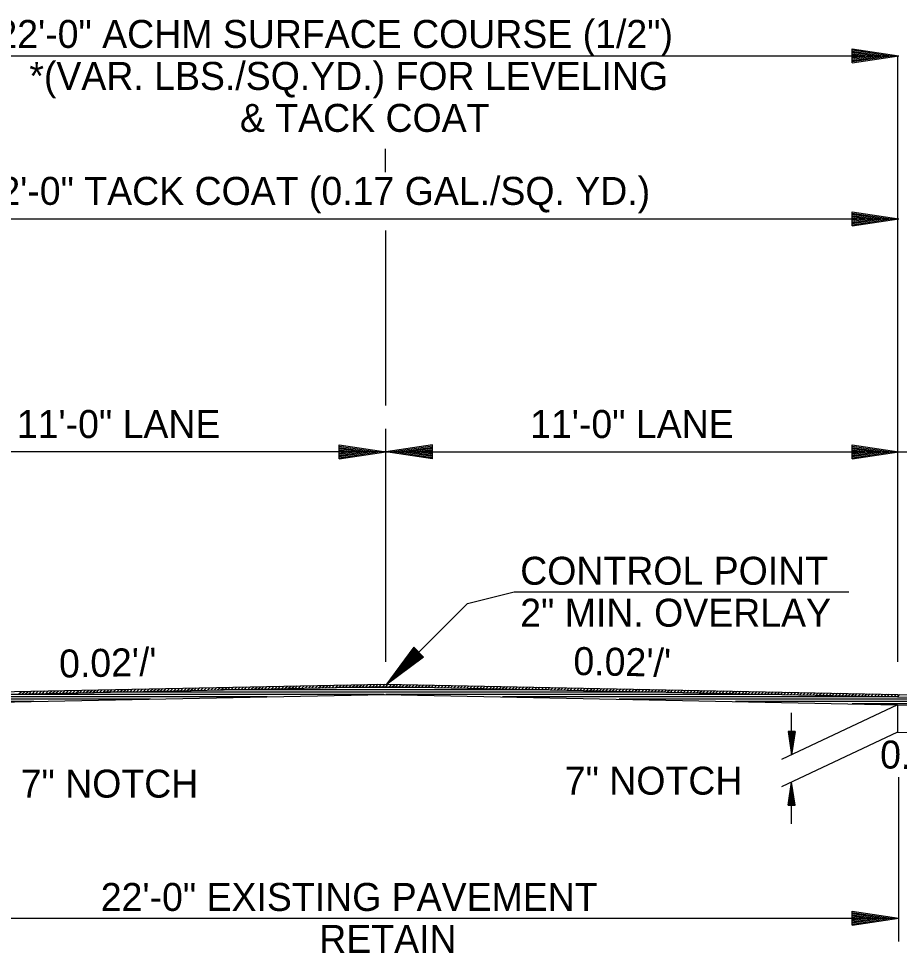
# Model space of a CAD drawing. Extents: x 2263886 to 2266026, y -3122850 to -3121850.
# Drawn here: x 2265472.89 to 2265491.77, y -3122426.95 to -3122407.14 of the extents above; entities that cross this region are included whole.
import ezdxf

# ---------------------------------------------------------------- set-up
doc = ezdxf.new("R2010")
doc.units = 0
doc.layers.add('R_Border Notes', color=7, linetype='Continuous')
doc.layers.add('R_Border Prem', color=7, linetype='Continuous')

msp = doc.modelspace()

# ---------------------------------------------------------------- linework, layer by layer
at = {"layer": 'R_Border Notes'}
for p, q in [((2265469.74, -3122421.686), (2265480.738, -3122421.466)), ((2265469.741, -3122421.634), (2265480.739, -3122421.414)), ((2265472.9, -3122421.622), (2265472.953, -3122421.569)), ((2265472.972, -3122421.621), (2265473.025, -3122421.568)), ((2265473.044, -3122421.62), (2265473.097, -3122421.567)), ((2265473.116, -3122421.618), (2265473.169, -3122421.565)), ((2265473.189, -3122421.617), (2265473.242, -3122421.564)), ((2265473.261, -3122421.615), (2265473.314, -3122421.562)), ((2265473.333, -3122421.614), (2265473.386, -3122421.561)), ((2265473.405, -3122421.612), (2265473.458, -3122421.559)), ((2265473.477, -3122421.611), (2265473.53, -3122421.558)), ((2265473.549, -3122421.609), (2265473.602, -3122421.556)), ((2265473.621, -3122421.608), (2265473.674, -3122421.555)), ((2265473.694, -3122421.607), (2265473.747, -3122421.554)), ((2265473.766, -3122421.605), (2265473.819, -3122421.552)), ((2265473.838, -3122421.604), (2265473.891, -3122421.551)), ((2265473.91, -3122421.602), (2265473.963, -3122421.549)), ((2265473.982, -3122421.601), (2265474.035, -3122421.548)), ((2265474.054, -3122421.599), (2265474.107, -3122421.546)), ((2265474.127, -3122421.598), (2265474.18, -3122421.545)), ((2265474.199, -3122421.596), (2265474.252, -3122421.543)), ((2265474.271, -3122421.595), (2265474.324, -3122421.542)), ((2265474.343, -3122421.594), (2265474.396, -3122421.541)), ((2265474.415, -3122421.592), (2265474.468, -3122421.539)), ((2265474.487, -3122421.591), (2265474.54, -3122421.538)), ((2265474.559, -3122421.589), (2265474.612, -3122421.536)), ((2265474.632, -3122421.588), (2265474.685, -3122421.535)), ((2265474.704, -3122421.586), (2265474.757, -3122421.533)), ((2265474.776, -3122421.585), (2265474.829, -3122421.532)), ((2265474.848, -3122421.583), (2265474.901, -3122421.53)), ((2265474.92, -3122421.582), (2265474.973, -3122421.529)), ((2265474.992, -3122421.581), (2265475.045, -3122421.528)), ((2265475.065, -3122421.579), (2265475.118, -3122421.526)), ((2265475.137, -3122421.578), (2265475.19, -3122421.525)), ((2265475.209, -3122421.576), (2265475.262, -3122421.523)), ((2265475.281, -3122421.575), (2265475.334, -3122421.522)), ((2265475.353, -3122421.573), (2265475.406, -3122421.52)), ((2265475.425, -3122421.572), (2265475.478, -3122421.519)), ((2265475.497, -3122421.57), (2265475.55, -3122421.517)), ((2265475.57, -3122421.569), (2265475.623, -3122421.516)), ((2265475.642, -3122421.568), (2265475.695, -3122421.515)), ((2265475.714, -3122421.566), (2265475.767, -3122421.513)), ((2265475.786, -3122421.565), (2265475.839, -3122421.512)), ((2265475.858, -3122421.563), (2265475.911, -3122421.51)), ((2265475.93, -3122421.562), (2265475.983, -3122421.509)), ((2265476.003, -3122421.56), (2265476.056, -3122421.507)), ((2265476.075, -3122421.559), (2265476.128, -3122421.506)), ((2265476.147, -3122421.557), (2265476.2, -3122421.504)), ((2265476.219, -3122421.556), (2265476.272, -3122421.503)), ((2265476.291, -3122421.555), (2265476.344, -3122421.502)), ((2265476.363, -3122421.553), (2265476.416, -3122421.5)), ((2265476.435, -3122421.552), (2265476.488, -3122421.499)), ((2265476.508, -3122421.55), (2265476.561, -3122421.497)), ((2265476.58, -3122421.549), (2265476.633, -3122421.496)), ((2265476.652, -3122421.547), (2265476.705, -3122421.494)), ((2265476.724, -3122421.546), (2265476.777, -3122421.493)), ((2265476.796, -3122421.545), (2265476.849, -3122421.491)), ((2265476.868, -3122421.543), (2265476.921, -3122421.49)), ((2265476.941, -3122421.542), (2265476.994, -3122421.489)), ((2265477.013, -3122421.54), (2265477.066, -3122421.487)), ((2265477.085, -3122421.539), (2265477.138, -3122421.486)), ((2265477.157, -3122421.537), (2265477.21, -3122421.484)), ((2265484.259, -3122421.536), (2265477.217, -3122421.536)), ((2265477.229, -3122421.536), (2265477.282, -3122421.483)), ((2265477.301, -3122421.534), (2265477.354, -3122421.481)), ((2265477.373, -3122421.533), (2265477.426, -3122421.48)), ((2265477.446, -3122421.532), (2265477.499, -3122421.478)), ((2265477.518, -3122421.53), (2265477.571, -3122421.477)), ((2265477.59, -3122421.529), (2265477.643, -3122421.476)), ((2265477.662, -3122421.527), (2265477.715, -3122421.474)), ((2265477.734, -3122421.526), (2265477.787, -3122421.473)), ((2265477.806, -3122421.524), (2265477.859, -3122421.471)), ((2265477.879, -3122421.523), (2265477.932, -3122421.47)), ((2265477.951, -3122421.521), (2265478.004, -3122421.468)), ((2265478.023, -3122421.52), (2265478.076, -3122421.467)), ((2265478.095, -3122421.519), (2265478.148, -3122421.465)), ((2265478.167, -3122421.517), (2265478.22, -3122421.464)), ((2265478.239, -3122421.516), (2265478.292, -3122421.463)), ((2265478.311, -3122421.514), (2265478.364, -3122421.461)), ((2265478.384, -3122421.513), (2265478.437, -3122421.46)), ((2265478.456, -3122421.511), (2265478.509, -3122421.458)), ((2265478.528, -3122421.51), (2265478.581, -3122421.457)), ((2265478.6, -3122421.508), (2265478.653, -3122421.455)), ((2265478.672, -3122421.507), (2265478.725, -3122421.454)), ((2265478.744, -3122421.506), (2265478.797, -3122421.453)), ((2265478.817, -3122421.504), (2265478.87, -3122421.451)), ((2265478.889, -3122421.503), (2265478.942, -3122421.45)), ((2265478.961, -3122421.501), (2265479.014, -3122421.448)), ((2265479.033, -3122421.5), (2265479.086, -3122421.447)), ((2265479.105, -3122421.498), (2265479.158, -3122421.445)), ((2265479.177, -3122421.497), (2265479.23, -3122421.444)), ((2265479.249, -3122421.495), (2265479.302, -3122421.442)), ((2265479.322, -3122421.494), (2265479.375, -3122421.441)), ((2265479.394, -3122421.493), (2265479.447, -3122421.44)), ((2265479.466, -3122421.491), (2265479.519, -3122421.438)), ((2265479.538, -3122421.49), (2265479.591, -3122421.437)), ((2265479.61, -3122421.488), (2265479.663, -3122421.435)), ((2265479.682, -3122421.487), (2265479.735, -3122421.434)), ((2265481.759, -3122421.486), (2265479.716, -3122421.486)), ((2265479.755, -3122421.485), (2265479.808, -3122421.432)), ((2265479.827, -3122421.484), (2265479.88, -3122421.431)), ((2265479.899, -3122421.482), (2265479.952, -3122421.429)), ((2265479.971, -3122421.481), (2265480.024, -3122421.428)), ((2265480.043, -3122421.48), (2265480.096, -3122421.427)), ((2265480.115, -3122421.478), (2265480.168, -3122421.425)), ((2265480.187, -3122421.477), (2265480.24, -3122421.424)), ((2265480.26, -3122421.475), (2265480.313, -3122421.422)), ((2265480.332, -3122421.474), (2265480.385, -3122421.421)), ((2265480.404, -3122421.472), (2265480.457, -3122421.419)), ((2265480.476, -3122421.471), (2265480.529, -3122421.418)), ((2265480.548, -3122421.469), (2265480.601, -3122421.416)), ((2265480.62, -3122421.468), (2265480.673, -3122421.415)), ((2265480.693, -3122421.467), (2265480.745, -3122421.414)), ((2265480.738, -3122421.466), (2265491.736, -3122421.686)), ((2265480.739, -3122421.414), (2265491.737, -3122421.634)), ((2265480.764, -3122421.466), (2265480.815, -3122421.415)), ((2265480.833, -3122421.468), (2265480.884, -3122421.417)), ((2265480.902, -3122421.469), (2265480.953, -3122421.418)), ((2265480.972, -3122421.47), (2265481.023, -3122421.419)), ((2265481.041, -3122421.472), (2265481.092, -3122421.421)), ((2265481.11, -3122421.473), (2265481.161, -3122421.422)), ((2265481.18, -3122421.474), (2265481.231, -3122421.424)), ((2265481.249, -3122421.476), (2265481.3, -3122421.425)), ((2265481.318, -3122421.477), (2265481.369, -3122421.426)), ((2265481.388, -3122421.479), (2265481.439, -3122421.428)), ((2265481.457, -3122421.48), (2265481.508, -3122421.429)), ((2265481.526, -3122421.481), (2265481.577, -3122421.43)), ((2265481.596, -3122421.483), (2265481.647, -3122421.432)), ((2265481.665, -3122421.484), (2265481.716, -3122421.433)), ((2265481.734, -3122421.486), (2265481.785, -3122421.435)), ((2265481.804, -3122421.487), (2265481.854, -3122421.436)), ((2265481.873, -3122421.488), (2265481.924, -3122421.437)), ((2265481.942, -3122421.49), (2265481.993, -3122421.439)), ((2265482.011, -3122421.491), (2265482.062, -3122421.44)), ((2265482.081, -3122421.493), (2265482.132, -3122421.442)), ((2265482.15, -3122421.494), (2265482.201, -3122421.443)), ((2265482.219, -3122421.495), (2265482.27, -3122421.444)), ((2265482.289, -3122421.497), (2265482.34, -3122421.446)), ((2265482.358, -3122421.498), (2265482.409, -3122421.447)), ((2265482.427, -3122421.499), (2265482.478, -3122421.448)), ((2265482.497, -3122421.501), (2265482.548, -3122421.45)), ((2265482.566, -3122421.502), (2265482.617, -3122421.451)), ((2265482.635, -3122421.504), (2265482.686, -3122421.453)), ((2265482.705, -3122421.505), (2265482.756, -3122421.454)), ((2265482.774, -3122421.506), (2265482.825, -3122421.455)), ((2265482.843, -3122421.508), (2265482.894, -3122421.457)), ((2265482.913, -3122421.509), (2265482.964, -3122421.458)), ((2265482.982, -3122421.511), (2265483.033, -3122421.46)), ((2265483.051, -3122421.512), (2265483.102, -3122421.461)), ((2265483.121, -3122421.513), (2265483.172, -3122421.462)), ((2265483.19, -3122421.515), (2265483.241, -3122421.464)), ((2265483.259, -3122421.516), (2265483.31, -3122421.465)), ((2265483.329, -3122421.517), (2265483.38, -3122421.466)), ((2265483.398, -3122421.519), (2265483.449, -3122421.468)), ((2265483.467, -3122421.52), (2265483.518, -3122421.469)), ((2265483.537, -3122421.522), (2265483.588, -3122421.471)), ((2265483.606, -3122421.523), (2265483.657, -3122421.472)), ((2265483.675, -3122421.524), (2265483.726, -3122421.473)), ((2265483.745, -3122421.526), (2265483.796, -3122421.475)), ((2265483.814, -3122421.527), (2265483.865, -3122421.476)), ((2265483.883, -3122421.529), (2265483.934, -3122421.478)), ((2265483.953, -3122421.53), (2265484.004, -3122421.479)), ((2265484.022, -3122421.531), (2265484.073, -3122421.48)), ((2265484.091, -3122421.533), (2265484.142, -3122421.482)), ((2265484.161, -3122421.534), (2265484.212, -3122421.483)), ((2265484.23, -3122421.536), (2265484.281, -3122421.485)), ((2265484.299, -3122421.537), (2265484.35, -3122421.486)), ((2265484.368, -3122421.538), (2265484.419, -3122421.487)), ((2265484.438, -3122421.54), (2265484.489, -3122421.489)), ((2265484.507, -3122421.541), (2265484.558, -3122421.49)), ((2265484.576, -3122421.542), (2265484.627, -3122421.491)), ((2265484.646, -3122421.544), (2265484.697, -3122421.493)), ((2265484.715, -3122421.545), (2265484.766, -3122421.494)), ((2265484.784, -3122421.547), (2265484.835, -3122421.496)), ((2265484.854, -3122421.548), (2265484.905, -3122421.497)), ((2265484.923, -3122421.549), (2265484.974, -3122421.498)), ((2265484.992, -3122421.551), (2265485.043, -3122421.5)), ((2265485.062, -3122421.552), (2265485.113, -3122421.501)), ((2265485.131, -3122421.554), (2265485.182, -3122421.503)), ((2265485.2, -3122421.555), (2265485.251, -3122421.504)), ((2265485.27, -3122421.556), (2265485.321, -3122421.505)), ((2265485.339, -3122421.558), (2265485.39, -3122421.507)), ((2265485.408, -3122421.559), (2265485.459, -3122421.508)), ((2265485.478, -3122421.56), (2265485.529, -3122421.509)), ((2265485.547, -3122421.562), (2265485.598, -3122421.511)), ((2265485.616, -3122421.563), (2265485.667, -3122421.512)), ((2265485.686, -3122421.565), (2265485.737, -3122421.514)), ((2265485.755, -3122421.566), (2265485.806, -3122421.515)), ((2265485.824, -3122421.567), (2265485.875, -3122421.516)), ((2265485.894, -3122421.569), (2265485.945, -3122421.518)), ((2265485.963, -3122421.57), (2265486.014, -3122421.519)), ((2265486.032, -3122421.572), (2265486.083, -3122421.521)), ((2265486.102, -3122421.573), (2265486.153, -3122421.522)), ((2265486.171, -3122421.574), (2265486.222, -3122421.523)), ((2265486.24, -3122421.576), (2265486.291, -3122421.525)), ((2265486.31, -3122421.577), (2265486.361, -3122421.526)), ((2265486.379, -3122421.579), (2265486.43, -3122421.528)), ((2265486.448, -3122421.58), (2265486.499, -3122421.529)), ((2265486.518, -3122421.581), (2265486.569, -3122421.53)), ((2265486.587, -3122421.583), (2265486.638, -3122421.532)), ((2265486.656, -3122421.584), (2265486.707, -3122421.533)), ((2265486.725, -3122421.585), (2265486.776, -3122421.534)), ((2265486.795, -3122421.587), (2265486.846, -3122421.536)), ((2265486.864, -3122421.588), (2265486.915, -3122421.537)), ((2265486.933, -3122421.59), (2265486.984, -3122421.539)), ((2265487.003, -3122421.591), (2265487.054, -3122421.54)), ((2265487.072, -3122421.592), (2265487.123, -3122421.541)), ((2265487.141, -3122421.594), (2265487.192, -3122421.543)), ((2265487.211, -3122421.595), (2265487.262, -3122421.544)), ((2265487.28, -3122421.597), (2265487.331, -3122421.546)), ((2265487.349, -3122421.598), (2265487.4, -3122421.547)), ((2265487.419, -3122421.599), (2265487.47, -3122421.548)), ((2265487.488, -3122421.601), (2265487.539, -3122421.55)), ((2265487.557, -3122421.602), (2265487.608, -3122421.551)), ((2265487.627, -3122421.603), (2265487.678, -3122421.552)), ((2265487.696, -3122421.605), (2265487.747, -3122421.554)), ((2265487.765, -3122421.606), (2265487.816, -3122421.555)), ((2265487.835, -3122421.608), (2265487.886, -3122421.557)), ((2265487.904, -3122421.609), (2265487.955, -3122421.558)), ((2265487.973, -3122421.61), (2265488.024, -3122421.559)), ((2265488.043, -3122421.612), (2265488.094, -3122421.561)), ((2265488.112, -3122421.613), (2265488.163, -3122421.562)), ((2265488.181, -3122421.615), (2265488.232, -3122421.564)), ((2265488.251, -3122421.616), (2265488.302, -3122421.565)), ((2265488.32, -3122421.617), (2265488.371, -3122421.566)), ((2265488.389, -3122421.619), (2265488.44, -3122421.568)), ((2265488.459, -3122421.62), (2265488.51, -3122421.569)), ((2265488.528, -3122421.621), (2265488.579, -3122421.571)), ((2265488.597, -3122421.623), (2265488.648, -3122421.572)), ((2265488.667, -3122421.624), (2265488.718, -3122421.573)), ((2265488.736, -3122421.626), (2265488.787, -3122421.575)), ((2265488.805, -3122421.627), (2265488.856, -3122421.576)), ((2265488.875, -3122421.628), (2265488.926, -3122421.577)), ((2265475.719, -3122421.736), (2265467.735, -3122421.736)), ((2265478.218, -3122421.686), (2265469.718, -3122421.686)), ((2265469.743, -3122421.856), (2265480.741, -3122421.636)), ((2265480.718, -3122421.636), (2265472.218, -3122421.636)), ((2265486.758, -3122421.586), (2265474.717, -3122421.586)), ((2265480.734, -3122421.636), (2265491.732, -3122421.856)), ((2265489.258, -3122421.636), (2265480.764, -3122421.636)), ((2265491.757, -3122421.686), (2265483.262, -3122421.686)), ((2265493.74, -3122421.736), (2265485.76, -3122421.736)), ((2265488.944, -3122421.63), (2265488.995, -3122421.579)), ((2265489.013, -3122421.631), (2265489.064, -3122421.58)), ((2265489.083, -3122421.633), (2265489.134, -3122421.582)), ((2265489.152, -3122421.634), (2265489.203, -3122421.583)), ((2265489.221, -3122421.635), (2265489.272, -3122421.584)), ((2265489.29, -3122421.637), (2265489.341, -3122421.586)), ((2265489.36, -3122421.638), (2265489.411, -3122421.587)), ((2265489.429, -3122421.64), (2265489.48, -3122421.589)), ((2265489.498, -3122421.641), (2265489.549, -3122421.59)), ((2265489.568, -3122421.642), (2265489.619, -3122421.591)), ((2265489.637, -3122421.644), (2265489.688, -3122421.593)), ((2265489.706, -3122421.645), (2265489.757, -3122421.594)), ((2265489.776, -3122421.646), (2265489.827, -3122421.595)), ((2265489.845, -3122421.648), (2265489.896, -3122421.597)), ((2265489.914, -3122421.649), (2265489.965, -3122421.598)), ((2265489.984, -3122421.651), (2265490.035, -3122421.6)), ((2265490.053, -3122421.652), (2265490.104, -3122421.601)), ((2265490.122, -3122421.653), (2265490.173, -3122421.602)), ((2265490.192, -3122421.655), (2265490.243, -3122421.604)), ((2265490.261, -3122421.656), (2265490.312, -3122421.605)), ((2265490.33, -3122421.658), (2265490.381, -3122421.607)), ((2265490.4, -3122421.659), (2265490.451, -3122421.608)), ((2265490.469, -3122421.66), (2265490.52, -3122421.609)), ((2265490.538, -3122421.662), (2265490.589, -3122421.611)), ((2265490.608, -3122421.663), (2265490.659, -3122421.612)), ((2265490.677, -3122421.664), (2265490.728, -3122421.613)), ((2265490.746, -3122421.666), (2265490.797, -3122421.615)), ((2265490.816, -3122421.667), (2265490.867, -3122421.616)), ((2265490.885, -3122421.669), (2265490.936, -3122421.618)), ((2265490.954, -3122421.67), (2265491.005, -3122421.619)), ((2265491.024, -3122421.671), (2265491.075, -3122421.62)), ((2265491.093, -3122421.673), (2265491.144, -3122421.622)), ((2265491.162, -3122421.674), (2265491.213, -3122421.623)), ((2265491.232, -3122421.676), (2265491.283, -3122421.625)), ((2265491.301, -3122421.677), (2265491.352, -3122421.626)), ((2265491.37, -3122421.678), (2265491.421, -3122421.627)), ((2265491.44, -3122421.68), (2265491.491, -3122421.629)), ((2265491.509, -3122421.681), (2265491.56, -3122421.63)), ((2265491.578, -3122421.683), (2265491.629, -3122421.632)), ((2265491.647, -3122421.684), (2265491.698, -3122421.633)), ((2265491.717, -3122421.685), (2265491.768, -3122421.634)), ((2265491.736, -3122421.686), (2265493.735, -3122421.726)), ((2265491.737, -3122421.634), (2265493.736, -3122421.674)), ((2265473.219, -3122421.786), (2265467.71, -3122421.786)), ((2265493.765, -3122421.786), (2265488.258, -3122421.786)), ((2265493.79, -3122421.836), (2265490.756, -3122421.836)), ((2265491.732, -3122421.856), (2265493.821, -3122421.897)), ((2265491.732, -3122421.856), (2265491.732, -3122422.439)), ((2265491.732, -3122422.439), (2265495.305, -3122422.51))]:
    msp.add_line(p, q, dxfattribs=at)
at = {"layer": 'R_Border Prem'}
for p, q in [((2265490.76, -3122407.783), (2265491.76, -3122407.933)), ((2265490.76, -3122408.083), (2265490.76, -3122407.783)), ((2265490.76, -3122407.808), (2265491.593, -3122407.933)), ((2265490.76, -3122407.834), (2265491.421, -3122407.933)), ((2265490.76, -3122407.859), (2265491.255, -3122407.933)), ((2265490.76, -3122407.884), (2265491.085, -3122407.933)), ((2265469.74, -3122407.933), (2265491.76, -3122407.933)), ((2265490.76, -3122407.91), (2265490.918, -3122407.933)), ((2265490.76, -3122408.083), (2265491.76, -3122407.933)), ((2265490.76, -3122407.982), (2265491.085, -3122407.933)), ((2265490.76, -3122408.033), (2265491.421, -3122407.933)), ((2265490.76, -3122408.058), (2265491.593, -3122407.933)), ((2265490.76, -3122408.008), (2265491.255, -3122407.933)), ((2265490.76, -3122407.957), (2265490.918, -3122407.933)), ((2265491.736, -3122420.933), (2265491.736, -3122407.933)), ((2265480.757, -3122410.433), (2265480.757, -3122409.933)), ((2265469.76, -3122411.433), (2265491.76, -3122411.433)), ((2265490.76, -3122411.283), (2265491.76, -3122411.433)), ((2265490.76, -3122411.583), (2265490.76, -3122411.283)), ((2265490.76, -3122411.308), (2265491.593, -3122411.433)), ((2265490.76, -3122411.334), (2265491.421, -3122411.433)), ((2265490.76, -3122411.359), (2265491.255, -3122411.433)), ((2265490.76, -3122411.384), (2265491.085, -3122411.433)), ((2265490.76, -3122411.41), (2265490.918, -3122411.433)), ((2265490.76, -3122411.583), (2265491.76, -3122411.433)), ((2265490.76, -3122411.482), (2265491.085, -3122411.433)), ((2265490.76, -3122411.533), (2265491.421, -3122411.433)), ((2265490.76, -3122411.558), (2265491.593, -3122411.433)), ((2265490.76, -3122411.508), (2265491.255, -3122411.433)), ((2265490.76, -3122411.457), (2265490.918, -3122411.433)), ((2265480.76, -3122415.433), (2265480.76, -3122411.683)), ((2265480.76, -3122420.933), (2265480.76, -3122415.933)), ((2265479.76, -3122416.283), (2265480.76, -3122416.433)), ((2265479.76, -3122416.583), (2265479.76, -3122416.283)), ((2265479.76, -3122416.308), (2265480.593, -3122416.433)), ((2265479.76, -3122416.334), (2265480.421, -3122416.433)), ((2265479.76, -3122416.359), (2265480.255, -3122416.433)), ((2265479.76, -3122416.384), (2265480.085, -3122416.433)), ((2265479.76, -3122416.41), (2265479.918, -3122416.433)), ((2265481.76, -3122416.283), (2265480.76, -3122416.433)), ((2265481.76, -3122416.308), (2265480.927, -3122416.433)), ((2265481.76, -3122416.334), (2265481.099, -3122416.433)), ((2265481.76, -3122416.359), (2265481.266, -3122416.433)), ((2265481.76, -3122416.384), (2265481.435, -3122416.433)), ((2265481.76, -3122416.41), (2265481.602, -3122416.433)), ((2265481.76, -3122416.583), (2265481.76, -3122416.283)), ((2265490.76, -3122416.283), (2265491.76, -3122416.433)), ((2265490.76, -3122416.583), (2265490.76, -3122416.283)), ((2265490.76, -3122416.308), (2265491.593, -3122416.433)), ((2265490.76, -3122416.334), (2265491.421, -3122416.433)), ((2265490.76, -3122416.359), (2265491.255, -3122416.433)), ((2265490.76, -3122416.384), (2265491.085, -3122416.433)), ((2265490.76, -3122416.41), (2265490.918, -3122416.433)), ((2265480.76, -3122416.433), (2265469.76, -3122416.433)), ((2265479.76, -3122416.583), (2265480.76, -3122416.433)), ((2265479.76, -3122416.482), (2265480.085, -3122416.433)), ((2265479.76, -3122416.533), (2265480.421, -3122416.433)), ((2265479.76, -3122416.558), (2265480.593, -3122416.433)), ((2265479.76, -3122416.508), (2265480.255, -3122416.433)), ((2265479.76, -3122416.457), (2265479.918, -3122416.433)), ((2265480.76, -3122416.433), (2265491.76, -3122416.433)), ((2265481.76, -3122416.583), (2265480.76, -3122416.433)), ((2265481.76, -3122416.558), (2265480.927, -3122416.433)), ((2265481.76, -3122416.533), (2265481.099, -3122416.433)), ((2265481.76, -3122416.508), (2265481.266, -3122416.433)), ((2265481.76, -3122416.482), (2265481.435, -3122416.433)), ((2265481.76, -3122416.457), (2265481.602, -3122416.433)), ((2265490.76, -3122416.583), (2265491.76, -3122416.433)), ((2265490.76, -3122416.482), (2265491.085, -3122416.433)), ((2265490.76, -3122416.533), (2265491.421, -3122416.433)), ((2265490.76, -3122416.558), (2265491.593, -3122416.433)), ((2265490.76, -3122416.508), (2265491.255, -3122416.433)), ((2265490.76, -3122416.457), (2265490.918, -3122416.433)), ((2265491.76, -3122416.433), (2265500.665, -3122416.433)), ((2265482.51, -3122419.683), (2265483.51, -3122419.433)), ((2265483.51, -3122419.433), (2265490.687, -3122419.433)), ((2265480.76, -3122421.433), (2265482.51, -3122419.683)), ((2265481.361, -3122420.62), (2265480.76, -3122421.433)), ((2265481.379, -3122420.638), (2265480.878, -3122421.315)), ((2265481.397, -3122420.656), (2265481, -3122421.194)), ((2265481.414, -3122420.673), (2265481.117, -3122421.076)), ((2265481.52, -3122420.779), (2265481.117, -3122421.076)), ((2265481.432, -3122420.691), (2265481.237, -3122420.956)), ((2265481.501, -3122420.76), (2265481.237, -3122420.956)), ((2265481.45, -3122420.71), (2265481.355, -3122420.838)), ((2265481.484, -3122420.743), (2265481.355, -3122420.838)), ((2265481.573, -3122420.832), (2265481.361, -3122420.62)), ((2265481.573, -3122420.832), (2265480.76, -3122421.433)), ((2265481.555, -3122420.815), (2265480.878, -3122421.315)), ((2265481.537, -3122420.796), (2265481, -3122421.194)), ((2265491.732, -3122421.856), (2265489.244, -3122423.028)), ((2265489.457, -3122422.927), (2265489.457, -3122422.027)), ((2265491.732, -3122422.439), (2265489.244, -3122423.611)), ((2265489.382, -3122422.427), (2265489.457, -3122422.927)), ((2265489.532, -3122422.427), (2265489.382, -3122422.427)), ((2265489.395, -3122422.427), (2265489.457, -3122422.844)), ((2265489.407, -3122422.427), (2265489.457, -3122422.758)), ((2265489.42, -3122422.427), (2265489.457, -3122422.675)), ((2265489.433, -3122422.427), (2265489.457, -3122422.59)), ((2265489.445, -3122422.427), (2265489.457, -3122422.506)), ((2265489.532, -3122422.427), (2265489.457, -3122422.927)), ((2265489.481, -3122422.427), (2265489.457, -3122422.59)), ((2265489.507, -3122422.427), (2265489.457, -3122422.758)), ((2265489.52, -3122422.427), (2265489.457, -3122422.844)), ((2265489.494, -3122422.427), (2265489.457, -3122422.675)), ((2265489.469, -3122422.427), (2265489.457, -3122422.506)), ((2265489.382, -3122424.011), (2265489.457, -3122423.511)), ((2265489.532, -3122424.011), (2265489.457, -3122423.511)), ((2265489.457, -3122424.411), (2265489.457, -3122423.511)), ((2265491.76, -3122426.933), (2265491.76, -3122423.404)), ((2265489.395, -3122424.011), (2265489.457, -3122423.594)), ((2265489.407, -3122424.011), (2265489.457, -3122423.68)), ((2265489.52, -3122424.011), (2265489.457, -3122423.594)), ((2265489.507, -3122424.011), (2265489.457, -3122423.68)), ((2265489.42, -3122424.011), (2265489.457, -3122423.763)), ((2265489.433, -3122424.011), (2265489.457, -3122423.848)), ((2265489.445, -3122424.011), (2265489.457, -3122423.932)), ((2265489.494, -3122424.011), (2265489.457, -3122423.763)), ((2265489.482, -3122424.011), (2265489.457, -3122423.848)), ((2265489.469, -3122424.011), (2265489.457, -3122423.932)), ((2265489.382, -3122424.011), (2265489.532, -3122424.011)), ((2265490.76, -3122426.283), (2265491.76, -3122426.433)), ((2265490.76, -3122426.583), (2265490.76, -3122426.283)), ((2265490.76, -3122426.308), (2265491.593, -3122426.433)), ((2265490.76, -3122426.334), (2265491.421, -3122426.433)), ((2265469.76, -3122426.433), (2265491.76, -3122426.433)), ((2265490.76, -3122426.359), (2265491.255, -3122426.433)), ((2265490.76, -3122426.384), (2265491.085, -3122426.433)), ((2265490.76, -3122426.41), (2265490.918, -3122426.433)), ((2265490.76, -3122426.583), (2265491.76, -3122426.433)), ((2265490.76, -3122426.482), (2265491.085, -3122426.433)), ((2265490.76, -3122426.533), (2265491.421, -3122426.433)), ((2265490.76, -3122426.558), (2265491.593, -3122426.433)), ((2265490.76, -3122426.508), (2265491.255, -3122426.433)), ((2265490.76, -3122426.457), (2265490.918, -3122426.433))]:
    msp.add_line(p, q, dxfattribs=at)

# ---------------------------------------------------------------- texts
for s, rotation, p in [('22\'-0" ACHM SURFACE COURSE (1/2")', 360, (2265472.417, -3122407.767)), ('*(VAR. LBS./SQ.YD.) FOR LEVELING', 360, (2265473.123, -3122408.667)), ('& TACK COAT', 360, (2265477.635, -3122409.567)), ('22\'-0" TACK COAT (0.17 GAL./SQ. YD.)', 360, (2265472.034, -3122411.133)), ("0.02'/'", 1.1458, (2265473.766, -3122421.273)), ("0.02'/'", 358.8542, (2265484.778, -3122421.214)), ("0.02'/'", 358.8542, (2265491.351, -3122423.218)), ('22\'-0" EXISTING PAVEMENT', 360, (2265474.654, -3122426.276)), ('RETAIN', 360, (2265479.336, -3122427.176))]:
    msp.add_text(s, height=0.6, rotation=rotation, dxfattribs=at).set_placement(p)
for s, p in [('11\'-0" LANE', (2265472.855, -3122416.133)), ('11\'-0" LANE', (2265483.855, -3122416.133)), ('CONTROL POINT', (2265483.643, -3122419.28)), ('2" MIN. OVERLAY', (2265483.643, -3122420.18)), ('7" NOTCH', (2265472.937, -3122423.846)), ('7" NOTCH', (2265484.598, -3122423.782))]:
    msp.add_text(s, height=0.6, dxfattribs=at).set_placement(p)

doc.saveas('drawing.dxf')
